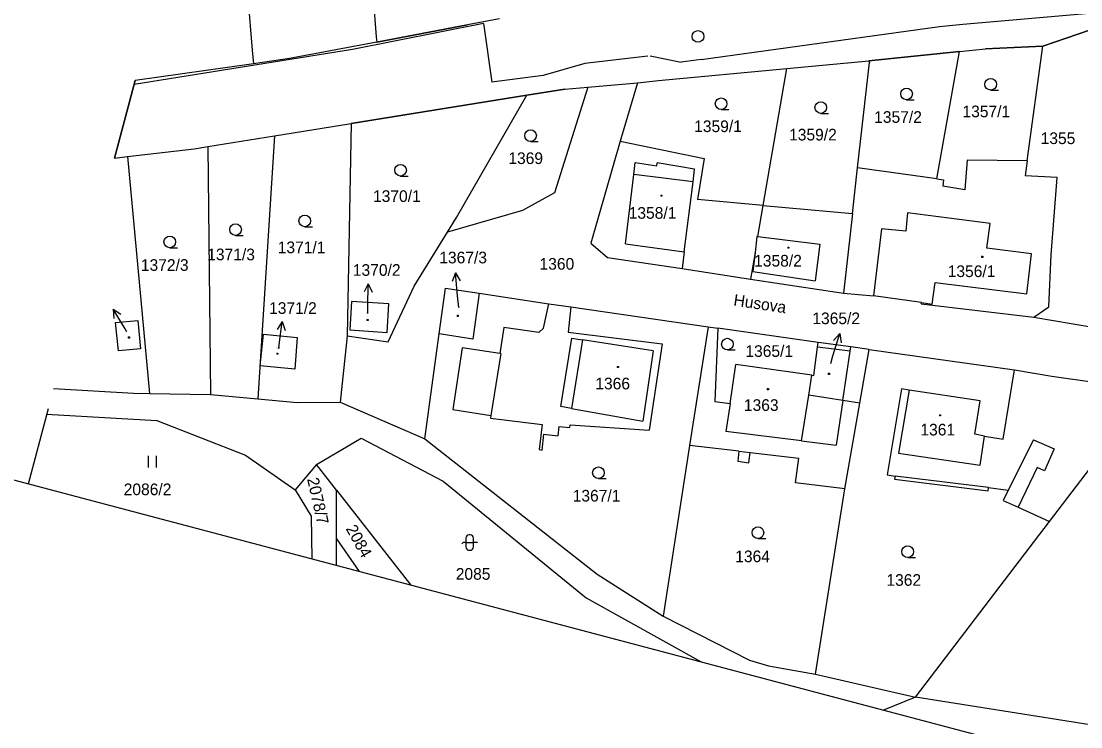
# Model space of a CAD drawing. Extents: x -805011 to -803920, y -1150790 to -1150234.
# Drawn here: x -804809.2 to -804673, y -1150606.5 to -1150515.7 of the extents above; entities that cross this region are included whole.
import ezdxf

# ---------------------------------------------------------------- set-up
doc = ezdxf.new("R2010")
doc.units = 0
for name, color, linetype in [('Default', 7, 'Continuous'), ('formát', 7, 'Continuous'), ('kilometráž - vrstava 7', 7, 'Continuous'), ('kn_celek - Cisla parcel pomocna', 7, 'Continuous'), ('kn_celek - Cisla pozemkovych parcel', 7, 'Continuous'), ('kn_celek - Cisla stavebnich parcel', 7, 'Continuous'), ('kn_celek - Dalsi prvky mapy popis', 7, 'Continuous'), ('kn_celek - Hranice parcel', 7, 'Continuous'), ('kn_celek - Vnitrni kresby', 7, 'Continuous'), ('kn_celek - Znacky budov', 7, 'Continuous'), ('kn_celek - Znacky kultur', 7, 'Continuous'), ('plochy - SZDC', 7, 'Continuous'), ('PSR_C2_2_trasa_Vimperk - Kabelová trasa', 7, 'Continuous')]:
    doc.layers.add(name, color=color, linetype=linetype)

# ---------------------------------------------------------------- blocks, each defined once
blk = doc.blocks.new('304')
at = {"layer": 'Default'}
blk.add_line((-0.1, 0), (9.9, 0), dxfattribs=at)
blk.add_circle((-0.1, 7.5), 7.5, dxfattribs=at)
blk = doc.blocks.new('316')
at = {"layer": 'Default'}
for p, q in [((-5, 15.5), (-5, 4.5)), ((0.5, 20), (-0.5, 20)), ((5, 4.5), (5, 15.5)), ((-8.3, 10), (-10, 8.1)), ((-5, 10), (-8.3, 10)), ((-5, 10), (5, 10)), ((-0.5, 0), (0.5, 0)), ((10, 10), (5, 10))]:
    blk.add_line(p, q, dxfattribs=at)
for centre, start, end in [((-0.5, 15.5), 90, 180), ((0.5, 15.5), 0, 90), ((-0.5, 4.5), 180, 270), ((0.5, 4.5), 270, 0)]:
    blk.add_arc(centre, 4.5, start, end, dxfattribs=at)
blk = doc.blocks.new('306')
at = {"layer": 'Default'}
for p, q in [((-5.2, 0), (-5.2, 15)), ((4.8, 0), (4.8, 15))]:
    blk.add_line(p, q, dxfattribs=at)
blk = doc.blocks.new('402')
at = {"layer": 'Default'}
for p, q in [((-0.8, 0.8), (0.7, 0.8)), ((-0.8, 0.8), (-0.8, -0.7)), ((0.7, 0.8), (0.7, -0.7)), ((0.7, -0.7), (-0.8, -0.7))]:
    blk.add_line(p, q, dxfattribs=at)
blk = doc.blocks.new('Z61')
at = {"layer": 'Default'}
for p, q in [((0, 0), (30, 0)), ((30, 0), (19.2, 5.3)), ((30, 0), (19.2, -5.3))]:
    blk.add_line(p, q, dxfattribs=at)

msp = doc.modelspace()

# ---------------------------------------------------------------- linework, layer by layer
at = {"layer": 'formát'}
for p, q in [((-804402.28, -1150682.7), (-805011.32, -1150521.54)), ((-804805.75, -1150565.59), (-804808.3, -1150575.26))]:
    msp.add_line(p, q, dxfattribs=at)
at = {"layer": 'kilometráž - vrstava 7'}
msp.add_circle((-804722.2, -1150517.67), 0.75, dxfattribs=at)
at = {"layer": 'kn_celek - Cisla parcel pomocna'}
for p, q in [((-804752.95, -1150552.55), (-804753.1, -1150551.06)), ((-804764.64, -1150553.33), (-804764.63, -1150552.48)), ((-804795.62, -1150555.68), (-804795.84, -1150555.31)), ((-804776.1, -1150557.81), (-804776.04, -1150557.34)), ((-804705.14, -1150559.73), (-804704.85, -1150558.77))]:
    msp.add_line(p, q, dxfattribs=at)
at = {"layer": 'kn_celek - Hranice parcel'}
for p, q in [((-804765.53, -1150494.1), (-804763.55, -1150517.73)), ((-804781.47, -1150495.86), (-804779.51, -1150519.42)), ((-804763.49, -1150518.4), (-804751.83, -1150516.2)), ((-804747.72, -1150515.43), (-804751.83, -1150516.2)), ((-804671.85, -1150516.86), (-804677.85, -1150518.93)), ((-804763.49, -1150518.4), (-804774.72, -1150520.52)), ((-804763.55, -1150517.73), (-804763.49, -1150518.4)), ((-804677.85, -1150518.93), (-804685.22, -1150519.25)), ((-804679.88, -1150533.68), (-804677.85, -1150518.93)), ((-804779.51, -1150519.42), (-804779.36, -1150521.18)), ((-804688.56, -1150519.6), (-804700.23, -1150520.83)), ((-804691.48, -1150536.01), (-804688.56, -1150519.6)), ((-804688.56, -1150519.6), (-804685.22, -1150519.25)), ((-804779.36, -1150521.18), (-804794.57, -1150523.35)), ((-804774.72, -1150520.52), (-804779.36, -1150521.18)), ((-804710.79, -1150521.81), (-804700.23, -1150520.83)), ((-804701.68, -1150534.6), (-804700.17, -1150521.02)), ((-804700.23, -1150520.83), (-804700.17, -1150521.02)), ((-804727.28, -1150523.34), (-804710.79, -1150521.81)), ((-804713.82, -1150539.42), (-804710.79, -1150521.81)), ((-804736.36, -1150524.18), (-804740.64, -1150537.81)), ((-804739.31, -1150524.46), (-804736.36, -1150524.18)), ((-804736.36, -1150524.18), (-804729.97, -1150523.63)), ((-804729.97, -1150523.63), (-804732.19, -1150531.16)), ((-804729.97, -1150523.63), (-804727.28, -1150523.34)), ((-804744.2, -1150525.25), (-804766.8, -1150528.89)), ((-804753.24, -1150540.95), (-804744.2, -1150525.25)), ((-804739.31, -1150524.46), (-804744.2, -1150525.25)), ((-804776.65, -1150530.47), (-804766.8, -1150528.89)), ((-804766.8, -1150528.89), (-804767.28, -1150556.21)), ((-804785.22, -1150531.85), (-804776.65, -1150530.47)), ((-804776.65, -1150530.47), (-804778.78, -1150564.3)), ((-804732.19, -1150531.16), (-804735.99, -1150544.25)), ((-804732.19, -1150531.16), (-804721.42, -1150533.39)), ((-804795.52, -1150533.13), (-804786.96, -1150532.13)), ((-804786.96, -1150532.13), (-804785.22, -1150531.85)), ((-804785.22, -1150531.85), (-804784.86, -1150563.74)), ((-804797.21, -1150533.33), (-804795.52, -1150533.13)), ((-804795.52, -1150533.13), (-804792.7, -1150563.59)), ((-804721.42, -1150533.39), (-804722.26, -1150538.65)), ((-804687.61, -1150533.6), (-804687.89, -1150537.42)), ((-804679.88, -1150533.68), (-804687.61, -1150533.6)), ((-804679.88, -1150533.68), (-804680.14, -1150535.59)), ((-804702.34, -1150540.46), (-804701.68, -1150534.6)), ((-804691.48, -1150536.01), (-804701.68, -1150534.6)), ((-804691.48, -1150536.01), (-804690.63, -1150536.13)), ((-804690.63, -1150536.13), (-804690.74, -1150536.92)), ((-804676.04, -1150535.83), (-804680.14, -1150535.59)), ((-804676.8, -1150545.77), (-804676.04, -1150535.83)), ((-804740.64, -1150537.81), (-804744.74, -1150540.06)), ((-804687.89, -1150537.42), (-804690.74, -1150536.92)), ((-804713.82, -1150539.42), (-804722.26, -1150538.65)), ((-804714.51, -1150543.42), (-804713.82, -1150539.42)), ((-804713.82, -1150539.42), (-804702.34, -1150540.46)), ((-804744.74, -1150540.06), (-804754.4, -1150542.84)), ((-804702.34, -1150540.46), (-804703.48, -1150550.7)), ((-804754.4, -1150542.84), (-804753.24, -1150540.95)), ((-804758.67, -1150549.81), (-804754.4, -1150542.84)), ((-804714.64, -1150543.4), (-804714.87, -1150545.49)), ((-804714.51, -1150543.42), (-804714.64, -1150543.4)), ((-804735.99, -1150544.25), (-804733.85, -1150546.1)), ((-804733.85, -1150546.1), (-804724.25, -1150547.55)), ((-804714.87, -1150545.49), (-804715.46, -1150548.88)), ((-804677.08, -1150552.48), (-804676.8, -1150545.77)), ((-804724.25, -1150547.55), (-804715.46, -1150548.88)), ((-804715.46, -1150548.88), (-804703.48, -1150550.7)), ((-804762.01, -1150556.95), (-804758.67, -1150549.81)), ((-804755.47, -1150555.94), (-804754.67, -1150550.06)), ((-804754.67, -1150550.06), (-804750.33, -1150550.72)), ((-804750.33, -1150550.72), (-804751.16, -1150556.62)), ((-804750.33, -1150550.72), (-804741.39, -1150552.08)), ((-804703.48, -1150550.7), (-804699.63, -1150551.04)), ((-804693.47, -1150551.91), (-804699.63, -1150551.04)), ((-804766.73, -1150551.77), (-804766.97, -1150555.44)), ((-804761.94, -1150552.09), (-804766.73, -1150551.77)), ((-804762.15, -1150555.77), (-804761.94, -1150552.09)), ((-804742.08, -1150555.2), (-804741.39, -1150552.08)), ((-804741.39, -1150552.08), (-804738.53, -1150552.46)), ((-804738.53, -1150552.46), (-804738.89, -1150555.74)), ((-804738.53, -1150552.46), (-804720.91, -1150555.02)), ((-804693.49, -1150552.09), (-804693.47, -1150551.91)), ((-804693.49, -1150552.09), (-804679.04, -1150553.78)), ((-804679.04, -1150553.78), (-804677.08, -1150552.48)), ((-804797.08, -1150554.49), (-804794.23, -1150554.22)), ((-804794.23, -1150554.22), (-804793.87, -1150557.85)), ((-804679.04, -1150553.78), (-804671.44, -1150555.09)), ((-804796.71, -1150558.14), (-804797.08, -1150554.49)), ((-804766.97, -1150555.44), (-804762.15, -1150555.77)), ((-804747.16, -1150555.14), (-804747.69, -1150558.46)), ((-804742.68, -1150555.76), (-804747.16, -1150555.14)), ((-804742.68, -1150555.76), (-804742.08, -1150555.2)), ((-804738.89, -1150555.74), (-804726.81, -1150557.24)), ((-804720.91, -1150555.02), (-804723.28, -1150570.3)), ((-804720.91, -1150555.02), (-804719.65, -1150555.2)), ((-804719.65, -1150555.2), (-804720.05, -1150564.62)), ((-804706.77, -1150557.03), (-804719.65, -1150555.2)), ((-804778.47, -1150560.05), (-804778.07, -1150555.99)), ((-804778.07, -1150555.99), (-804773.71, -1150556.42)), ((-804773.71, -1150556.42), (-804774.02, -1150560.49)), ((-804767.28, -1150556.21), (-804768.21, -1150564.72)), ((-804767.28, -1150556.21), (-804762.01, -1150556.95)), ((-804757.3, -1150569.44), (-804755.47, -1150555.94)), ((-804751.16, -1150556.62), (-804755.47, -1150555.94)), ((-804706.85, -1150557.64), (-804706.77, -1150557.03)), ((-804702.57, -1150557.62), (-804706.77, -1150557.03)), ((-804793.87, -1150557.85), (-804796.71, -1150558.14)), ((-804752.52, -1150557.74), (-804753.73, -1150565.68)), ((-804747.69, -1150558.46), (-804752.52, -1150557.74)), ((-804726.81, -1150557.24), (-804728.47, -1150568.34)), ((-804707.32, -1150561.31), (-804706.85, -1150557.64)), ((-804700.2, -1150557.94), (-804702.57, -1150557.62)), ((-804701.41, -1150564.85), (-804700.2, -1150557.94)), ((-804700.2, -1150557.94), (-804681.49, -1150560.57)), ((-804774.02, -1150560.49), (-804778.47, -1150560.05)), ((-804718.08, -1150564.9), (-804717.35, -1150559.9)), ((-804707.55, -1150561.25), (-804717.35, -1150559.9)), ((-804682.97, -1150569.49), (-804681.49, -1150560.57)), ((-804681.49, -1150560.57), (-804676.7, -1150561.39)), ((-804707.95, -1150563.81), (-804707.55, -1150561.25)), ((-804707.55, -1150561.25), (-804707.32, -1150561.31)), ((-804676.7, -1150561.39), (-804670.97, -1150562.21)), ((-804805.05, -1150562.96), (-804794.78, -1150563.55)), ((-804794.78, -1150563.55), (-804792.7, -1150563.59)), ((-804792.7, -1150563.59), (-804784.86, -1150563.74)), ((-804784.86, -1150563.74), (-804778.78, -1150564.3)), ((-804703.6, -1150564.5), (-804707.95, -1150563.81)), ((-804696.05, -1150563.02), (-804697.86, -1150574.08)), ((-804695.06, -1150563.17), (-804696.05, -1150563.02)), ((-804685.91, -1150564.57), (-804695.06, -1150563.17)), ((-804778.78, -1150564.3), (-804773.73, -1150564.76)), ((-804773.73, -1150564.76), (-804768.21, -1150564.72)), ((-804768.21, -1150564.72), (-804757.3, -1150569.44)), ((-804720.05, -1150564.62), (-804718.08, -1150564.9)), ((-804701.41, -1150564.85), (-804703.6, -1150564.5)), ((-804703.33, -1150575.86), (-804701.41, -1150564.85)), ((-804686.63, -1150568.85), (-804685.91, -1150564.57)), ((-804805.93, -1150566.29), (-804791.75, -1150567.1)), ((-804753.73, -1150565.68), (-804748.85, -1150566.42)), ((-804748.85, -1150566.42), (-804748.89, -1150566.77)), ((-804791.75, -1150567.1), (-804780.37, -1150571.54)), ((-804748.89, -1150566.77), (-804742.21, -1150567.6)), ((-804742.21, -1150567.6), (-804742.62, -1150570.83)), ((-804740.08, -1150567.87), (-804740.23, -1150569.07)), ((-804740.08, -1150567.87), (-804738.67, -1150567.97)), ((-804738.67, -1150567.97), (-804738.65, -1150567.62)), ((-804738.65, -1150567.62), (-804728.47, -1150568.34)), ((-804771.23, -1150572.75), (-804765.48, -1150569.34)), ((-804765.48, -1150569.34), (-804754.97, -1150574.87)), ((-804742.25, -1150570.88), (-804742, -1150568.85)), ((-804742, -1150568.85), (-804740.23, -1150569.07)), ((-804685.35, -1150569.09), (-804686.63, -1150568.85)), ((-804685.35, -1150569.09), (-804682.97, -1150569.49)), ((-804757.3, -1150569.44), (-804735.14, -1150586.85)), ((-804723.28, -1150570.3), (-804726.69, -1150592.24)), ((-804716.93, -1150571.04), (-804723.28, -1150570.3)), ((-804780.37, -1150571.54), (-804773.99, -1150576)), ((-804742.62, -1150570.83), (-804742.25, -1150570.88)), ((-804716.93, -1150571.04), (-804717.08, -1150572.33)), ((-804715.65, -1150572.54), (-804715.49, -1150571.21)), ((-804715.49, -1150571.21), (-804709.22, -1150571.94)), ((-804709.68, -1150575.1), (-804709.22, -1150571.94)), ((-804677.01, -1150580.07), (-804670.08, -1150570.98)), ((-804771.23, -1150572.75), (-804773.99, -1150576)), ((-804768.67, -1150576.05), (-804771.23, -1150572.75)), ((-804717.08, -1150572.33), (-804715.65, -1150572.54)), ((-804697.86, -1150574.08), (-804696.86, -1150574.23)), ((-804696.86, -1150574.23), (-804696.95, -1150574.63)), ((-804696.95, -1150574.63), (-804684.89, -1150576.12)), ((-804773.99, -1150576), (-804771.91, -1150579.38)), ((-804768.67, -1150582.3), (-804768.67, -1150576.05)), ((-804768.67, -1150576.05), (-804759.12, -1150588.27)), ((-804754.97, -1150574.87), (-804736.59, -1150589.91)), ((-804703.33, -1150575.86), (-804709.68, -1150575.1)), ((-804707.1, -1150599.7), (-804703.33, -1150575.86)), ((-804684.89, -1150576.12), (-804684.84, -1150575.72)), ((-804684.84, -1150575.72), (-804682.31, -1150576.03)), ((-804682.31, -1150576.03), (-804682.98, -1150577.37)), ((-804682.98, -1150577.37), (-804681.05, -1150578.24)), ((-804681.05, -1150578.24), (-804677.01, -1150580.07)), ((-804771.91, -1150579.38), (-804771.84, -1150584.91)), ((-804694.22, -1150602.66), (-804677.01, -1150580.07)), ((-804768.67, -1150585.75), (-804768.67, -1150582.3)), ((-804768.67, -1150582.3), (-804765.74, -1150586.52)), ((-804735.14, -1150586.85), (-804726.69, -1150592.24)), ((-804736.59, -1150589.91), (-804721.8, -1150598.15)), ((-804726.69, -1150592.24), (-804715.56, -1150597.91)), ((-804715.56, -1150597.91), (-804713.12, -1150598.64)), ((-804713.12, -1150598.64), (-804707.1, -1150599.7)), ((-804707.1, -1150599.7), (-804694.22, -1150602.66)), ((-804694.22, -1150602.66), (-804698.35, -1150604.35)), ((-804653.81, -1150609.12), (-804694.22, -1150602.66))]:
    msp.add_line(p, q, dxfattribs=at)
at = {"layer": 'kn_celek - Vnitrni kresby'}
for p, q in [((-804730.44, -1150535.43), (-804730.29, -1150533.9)), ((-804730.29, -1150533.9), (-804727.51, -1150534.31)), ((-804727.51, -1150534.31), (-804727.44, -1150533.95)), ((-804722.63, -1150534.73), (-804727.44, -1150533.95)), ((-804722.82, -1150536.38), (-804722.63, -1150534.73)), ((-804731.53, -1150544.37), (-804730.44, -1150535.43)), ((-804722.82, -1150536.38), (-804730.44, -1150535.43)), ((-804723.97, -1150545.37), (-804722.82, -1150536.38)), ((-804695.25, -1150540.37), (-804695.49, -1150542.73)), ((-804684.65, -1150541.76), (-804695.25, -1150540.37)), ((-804685.06, -1150544.92), (-804684.65, -1150541.76)), ((-804714.51, -1150543.42), (-804706.54, -1150544.38)), ((-804698.62, -1150542.42), (-804699.63, -1150551.04)), ((-804695.49, -1150542.73), (-804698.62, -1150542.42)), ((-804731.53, -1150544.37), (-804723.97, -1150545.37)), ((-804706.54, -1150544.38), (-804707.12, -1150549.13)), ((-804723.97, -1150545.37), (-804724.25, -1150547.55)), ((-804714.87, -1150545.49), (-804715.14, -1150547.92)), ((-804679.32, -1150545.66), (-804685.06, -1150544.92)), ((-804679.93, -1150550.77), (-804679.32, -1150545.66)), ((-804715.14, -1150547.92), (-804707.12, -1150549.13)), ((-804692.11, -1150552.1), (-804691.71, -1150549.33)), ((-804691.71, -1150549.33), (-804679.93, -1150550.77)), ((-804693.47, -1150551.91), (-804692.11, -1150552.1)), ((-804739.85, -1150565.28), (-804738.41, -1150556.49)), ((-804737.03, -1150556.7), (-804738.47, -1150565.53)), ((-804738.41, -1150556.49), (-804737.03, -1150556.7)), ((-804727.95, -1150558.1), (-804737.03, -1150556.7)), ((-804747.55, -1150558.47), (-804748.85, -1150566.42)), ((-804747.55, -1150558.47), (-804747.69, -1150558.46)), ((-804727.95, -1150558.1), (-804729.3, -1150567.19)), ((-804702.65, -1150558.17), (-804706.85, -1150557.64)), ((-804703.6, -1150564.5), (-804702.65, -1150558.17)), ((-804702.65, -1150558.17), (-804702.57, -1150557.62)), ((-804708.9, -1150569.7), (-804707.95, -1150563.81)), ((-804695.06, -1150563.17), (-804696.44, -1150571.27)), ((-804738.47, -1150565.53), (-804739.85, -1150565.28)), ((-804718.08, -1150564.9), (-804718.6, -1150568.49)), ((-804703.6, -1150564.5), (-804704.45, -1150570.25)), ((-804738.47, -1150565.53), (-804729.3, -1150567.19)), ((-804708.9, -1150569.7), (-804718.6, -1150568.49)), ((-804685.91, -1150572.82), (-804685.35, -1150569.09)), ((-804708.9, -1150569.7), (-804704.45, -1150570.25)), ((-804679.08, -1150569.57), (-804682.31, -1150576.03)), ((-804679.08, -1150569.57), (-804676.4, -1150570.73)), ((-804676.4, -1150570.73), (-804677.65, -1150573.57)), ((-804716.93, -1150571.04), (-804715.49, -1150571.21)), ((-804696.44, -1150571.27), (-804685.91, -1150572.82)), ((-804678.6, -1150573.12), (-804681.05, -1150578.24)), ((-804677.65, -1150573.57), (-804678.6, -1150573.12)), ((-804684.84, -1150575.72), (-804696.86, -1150574.23))]:
    msp.add_line(p, q, dxfattribs=at)
at = {"layer": 'plochy - SZDC'}
for p, q in [((-804751.83, -1150516.2), (-804763.49, -1150518.4)), ((-804747.72, -1150515.43), (-804751.83, -1150516.2)), ((-804677.85, -1150518.93), (-804671.85, -1150516.86)), ((-804763.49, -1150518.4), (-804774.72, -1150520.52)), ((-804685.22, -1150519.25), (-804677.85, -1150518.93)), ((-804700.23, -1150520.83), (-804688.56, -1150519.6)), ((-804688.56, -1150519.6), (-804685.22, -1150519.25)), ((-804779.36, -1150521.18), (-804794.57, -1150523.35)), ((-804774.72, -1150520.52), (-804779.36, -1150521.18)), ((-804710.79, -1150521.81), (-804700.23, -1150520.83)), ((-804727.28, -1150523.34), (-804710.79, -1150521.81)), ((-804797.21, -1150533.33), (-804794.57, -1150523.35)), ((-804794.57, -1150523.35), (-804797.21, -1150533.33)), ((-804739.31, -1150524.46), (-804736.36, -1150524.18)), ((-804736.36, -1150524.18), (-804729.97, -1150523.63)), ((-804729.97, -1150523.63), (-804727.28, -1150523.34)), ((-804766.8, -1150528.89), (-804744.2, -1150525.25)), ((-804744.2, -1150525.25), (-804739.31, -1150524.46)), ((-804776.65, -1150530.47), (-804766.8, -1150528.89)), ((-804785.22, -1150531.85), (-804776.65, -1150530.47)), ((-804795.52, -1150533.13), (-804786.96, -1150532.13)), ((-804786.96, -1150532.13), (-804785.22, -1150531.85)), ((-804797.21, -1150533.33), (-804795.52, -1150533.13))]:
    msp.add_line(p, q, dxfattribs=at)
at = {"layer": 'PSR_C2_2_trasa_Vimperk - Kabelová trasa'}
for p, q in [((-804688.16, -1150516.11), (-804664.5, -1150514.01)), ((-804749.78, -1150515.99), (-804766.6, -1150519.35)), ((-804749.78, -1150515.99), (-804748.68, -1150523.55)), ((-804691.14, -1150516.38), (-804688.16, -1150516.11)), ((-804721.8, -1150520.64), (-804691.14, -1150516.38)), ((-804728.64, -1150520.2), (-804736.74, -1150521.15)), ((-804728.36, -1150520.17), (-804724.38, -1150520.97)), ((-804736.74, -1150521.15), (-804742.12, -1150522.72)), ((-804721.8, -1150520.64), (-804724.38, -1150520.97)), ((-804742.12, -1150522.72), (-804748.68, -1150523.55))]:
    msp.add_line(p, q, dxfattribs=at)
msp.add_lwpolyline([(-804766.6, -1150519.35), (-804794.7, -1150523.84)], dxfattribs=at)

# ---------------------------------------------------------------- block references
at = {"layer": 'kn_celek - Cisla parcel pomocna'}
for p, xscale, yscale, rotation in [((-804753.1, -1150551.06), 0.09999999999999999, 0.10000000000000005, 95.59737000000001), ((-804764.63, -1150552.48), 0.1, 0.09999999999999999, 89.10720000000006), ((-804795.84, -1150555.31), 0.1, 0.09999999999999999, 121.27914000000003), ((-804776.04, -1150557.34), 0.1, 0.09999999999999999, 82.54719000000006), ((-804704.85, -1150558.77), 0.09999999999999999, 0.10000000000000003, 73.03959000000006)]:
    msp.add_blockref('Z61', p, dxfattribs=dict(at, xscale=xscale, yscale=yscale, rotation=rotation))
at = {"layer": 'kn_celek - Znacky budov', "xscale": 0.1, "yscale": 0.10000000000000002}
for p in [(-804726.9, -1150538.16), (-804710.58, -1150544.86), (-804685.67, -1150546.03), (-804764.67, -1150554.16), (-804753.09, -1150553.63), (-804795.36, -1150556.41), (-804776.27, -1150558.48), (-804732.49, -1150560.21), (-804705.37, -1150561.09), (-804713.22, -1150563.06), (-804691.09, -1150566.43)]:
    msp.add_blockref('402', p, dxfattribs=at)
at = {"layer": 'kn_celek - Znacky kultur', "xscale": 0.1, "yscale": 0.10000000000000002}
for name, p in [('304', (-804695.38, -1150525.82)), ('304', (-804684.56, -1150524.58)), ('304', (-804719.21, -1150527.08)), ('304', (-804706.4, -1150527.57)), ('304', (-804743.72, -1150531.19)), ('304', (-804760.43, -1150535.63)), ('304', (-804772.74, -1150542.15)), ('304', (-804781.64, -1150543.27)), ('304', (-804790.09, -1150544.86)), ('304', (-804718.41, -1150558.01)), ('306', (-804792.31, -1150573.15)), ('304', (-804734.98, -1150574.56)), ('304', (-804714.48, -1150582.26)), ('316', (-804751.55, -1150583.78)), ('304', (-804695.23, -1150584.71))]:
    msp.add_blockref(name, p, dxfattribs=at)

# ---------------------------------------------------------------- texts
at = {"layer": 'kn_celek - Cisla parcel pomocna'}
for s, p in [('1367/3', (-804755.46, -1150546.87)), ('1370/2', (-804766.57, -1150548.47)), ('1371/2', (-804777.34, -1150553.37)), ('1365/2', (-804707.5, -1150554.69))]:
    msp.add_text(s, height=1.5, dxfattribs=at).set_placement(p)
at = {"layer": 'kn_celek - Cisla pozemkovych parcel'}
for s, p in [('1357/1', (-804688.2, -1150528.07)), ('1359/1', (-804722.69, -1150529.98)), ('1357/2', (-804699.55, -1150528.79)), ('1359/2', (-804710.49, -1150531.06)), ('1355', (-804678.15, -1150531.52)), ('1369', (-804746.58, -1150534.09)), ('1370/1', (-804763.98, -1150538.97)), ('1371/1', (-804776.23, -1150545.56)), ('1371/3', (-804785.29, -1150546.47)), ('1360', (-804742.57, -1150547.68)), ('1372/3', (-804793.82, -1150547.83)), ('1365/1', (-804716.11, -1150558.9)), ('2086/2', (-804796.03, -1150576.69)), ('1367/1', (-804738.31, -1150577.51)), ('1364', (-804717.41, -1150585.31)), ('2085', (-804753.34, -1150587.57)), ('1362', (-804697.98, -1150588.35))]:
    msp.add_text(s, height=1.5, dxfattribs=at).set_placement(p)
for s, rotation, p in [('2078/7', 282.8076, (-804772.46, -1150574.6)), ('2084', 299.0926, (-804767.52, -1150581))]:
    msp.add_text(s, height=1.5, rotation=rotation, dxfattribs=at).set_placement(p)
at = {"layer": 'kn_celek - Cisla stavebnich parcel'}
for s, height, p in [('1358/1', 1.5, (-804731.11, -1150541.13)), ('1358/2', 1.5, (-804714.98, -1150547.28)), ('1356/1', 1.5, (-804690.1, -1150548.63)), ('1367/3', 0.1, (-804753.22, -1150552.52)), ('1370/2', 0.1, (-804764.91, -1150553.3)), ('1372/2', 0.1, (-804795.89, -1150555.65)), ('1371/2', 0.1, (-804776.36, -1150557.78)), ('1365/2', 0.1, (-804705.41, -1150559.7)), ('1366', 1.5, (-804735.4, -1150563.08)), ('1363', 1.5, (-804716.3, -1150565.85)), ('1361', 1.5, (-804693.61, -1150569.01))]:
    msp.add_text(s, height=height, dxfattribs=at).set_placement(p)
at = {"layer": 'kn_celek - Dalsi prvky mapy popis'}
msp.add_text('Husova', height=1.5, rotation=351.5394, dxfattribs=at).set_placement((-804717.7, -1150552.29))

doc.saveas('drawing.dxf')
